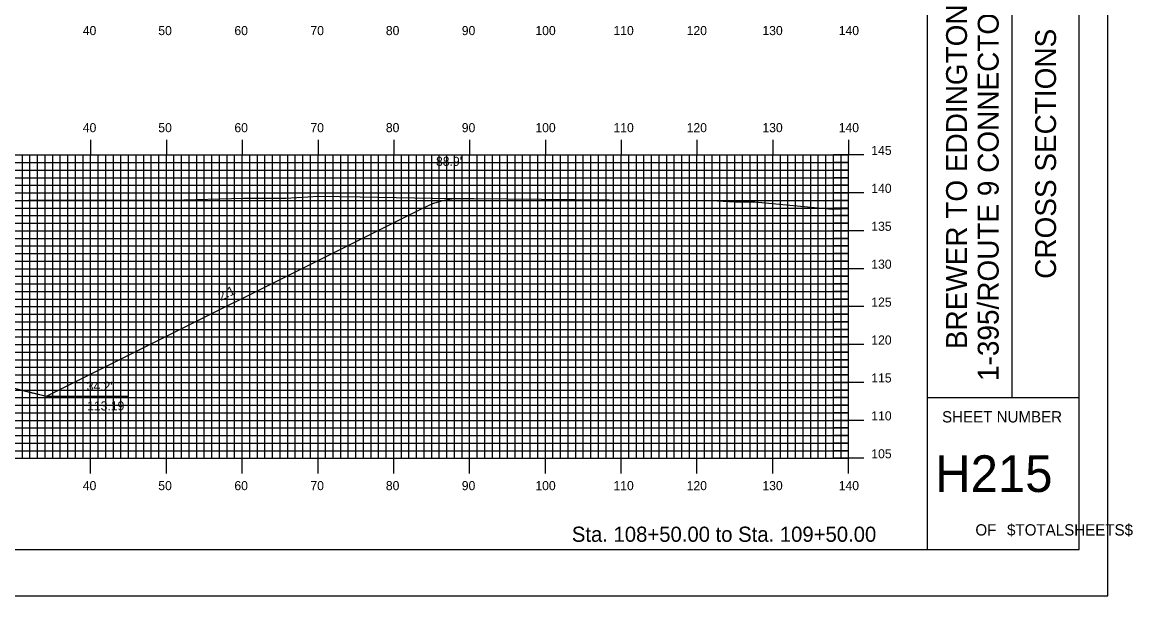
# Model space of a CAD drawing. Extents: x 1768874 to 1769217, y 442591 to 442811.
# Drawn here: x 1769071 to 1769217.5, y 442590.5 to 442666.2 of the extents above; entities that cross this region are included whole.
import ezdxf

# ---------------------------------------------------------------- set-up
doc = ezdxf.new("R2010")
doc.units = 0
for name, color, linetype in [('ANNOTATION', 7, 'Continuous'), ('BORDER', 7, 'Continuous'), ('D_Roadway_Centerline', 7, 'Continuous'), ('D_Roadway_SlopeLines', 7, 'Continuous'), ('D_Text_Standard', 7, 'Continuous'), ('H_V ANNOTATION', 7, 'Continuous'), ('MAJOR', 7, 'Continuous'), ('MINOR', 7, 'Continuous'), ('PDRAIN', 7, 'Continuous'), ('PLOT BOUNDARY', 7, 'Continuous'), ('S_Roadway_Centerline', 7, 'Continuous')]:
    doc.layers.add(name, color=color, linetype=linetype)

msp = doc.modelspace()

# ---------------------------------------------------------------- linework, layer by layer
at = {"layer": 'BORDER'}
for p, q in [((1769190.39, 442596.67), (1769190.39, 442806.67)), ((1769201.57, 442616.67), (1769201.57, 442686.67)), ((1769190.39, 442616.67), (1769210.39, 442616.67))]:
    msp.add_line(p, q, dxfattribs=at)
msp.add_lwpolyline([(1768890.39, 442596.67), (1769210.39, 442596.67), (1769210.39, 442806.67), (1768890.39, 442806.67)], close=True, dxfattribs=at)
at = {"layer": 'D_Roadway_Centerline'}
msp.add_lwpolyline([(1769070.16, 442617.85), (1769072.1, 442617.37), (1769074.16, 442616.85), (1769074.16, 442616.85), (1769123.9, 442641.72), (1769125.15, 442642.27), (1769126.4, 442642.65), (1769127.09, 442642.78), (1769127.65, 442642.88), (1769128.75, 442642.94), (1769128.9, 442642.95)], dxfattribs=at)
at = {"layer": 'D_Roadway_SlopeLines'}
for points in [[(1769074.16, 442616.85), (1769123.9, 442641.72), (1769125.15, 442642.27), (1769126.4, 442642.65), (1769127.65, 442642.88), (1769128.9, 442642.95)], [(1769059.99, 442620.4), (1769074.16, 442616.85)]]:
    msp.add_lwpolyline(points, dxfattribs=at)
at = {"layer": 'MAJOR'}
for p, q in [((1769079.99, 442650.67), (1769079.99, 442648.67)), ((1769089.99, 442650.67), (1769089.99, 442648.67)), ((1769099.99, 442650.67), (1769099.99, 442648.67)), ((1769109.99, 442650.67), (1769109.99, 442648.67)), ((1769119.99, 442650.67), (1769119.99, 442648.67)), ((1769129.99, 442650.67), (1769129.99, 442648.67)), ((1769139.99, 442650.67), (1769139.99, 442648.67)), ((1769149.99, 442650.67), (1769149.99, 442648.67)), ((1769159.99, 442650.67), (1769159.99, 442648.67)), ((1769169.99, 442650.67), (1769169.99, 442648.67)), ((1769179.99, 442650.67), (1769179.99, 442648.67)), ((1768899.99, 442648.67), (1769179.99, 442648.67)), ((1768899.99, 442648.67), (1769179.99, 442648.67)), ((1769079.99, 442608.67), (1769079.99, 442648.67)), ((1769089.99, 442608.67), (1769089.99, 442648.67)), ((1769099.99, 442608.67), (1769099.99, 442648.67)), ((1769109.99, 442608.67), (1769109.99, 442648.67)), ((1769119.99, 442608.67), (1769119.99, 442648.67)), ((1769129.99, 442608.67), (1769129.99, 442648.67)), ((1769139.99, 442608.67), (1769139.99, 442648.67)), ((1769149.99, 442608.67), (1769149.99, 442648.67)), ((1769159.99, 442608.67), (1769159.99, 442648.67)), ((1769169.99, 442608.67), (1769169.99, 442648.67)), ((1769181.99, 442648.67), (1769177.98, 442648.67)), ((1769179.99, 442608.67), (1769179.99, 442648.67)), ((1769179.99, 442608.67), (1769179.99, 442648.67)), ((1768899.99, 442643.67), (1769179.99, 442643.67)), ((1769181.99, 442643.67), (1769177.98, 442643.67)), ((1768899.99, 442638.67), (1769179.99, 442638.67)), ((1769181.99, 442638.67), (1769177.98, 442638.67)), ((1768899.99, 442633.67), (1769179.99, 442633.67)), ((1769181.99, 442633.67), (1769177.98, 442633.67)), ((1768899.99, 442628.67), (1769179.99, 442628.67)), ((1769181.99, 442628.67), (1769177.98, 442628.67)), ((1768899.99, 442623.67), (1769179.99, 442623.67)), ((1769181.99, 442623.67), (1769177.98, 442623.67)), ((1768899.99, 442618.67), (1769179.99, 442618.67)), ((1769181.99, 442618.67), (1769177.98, 442618.67)), ((1768899.99, 442613.67), (1769179.99, 442613.67)), ((1769181.99, 442613.67), (1769177.98, 442613.67)), ((1768899.99, 442608.67), (1769179.99, 442608.67)), ((1768899.99, 442608.67), (1769179.99, 442608.67)), ((1769079.99, 442606.66), (1769079.99, 442608.67)), ((1769089.99, 442606.66), (1769089.99, 442608.67)), ((1769099.99, 442606.66), (1769099.99, 442608.67)), ((1769109.99, 442606.66), (1769109.99, 442608.67)), ((1769119.99, 442606.66), (1769119.99, 442608.67)), ((1769129.99, 442606.66), (1769129.99, 442608.67)), ((1769139.99, 442606.66), (1769139.99, 442608.67)), ((1769149.99, 442606.66), (1769149.99, 442608.67)), ((1769159.99, 442606.66), (1769159.99, 442608.67)), ((1769169.99, 442606.66), (1769169.99, 442608.67)), ((1769181.99, 442608.67), (1769177.98, 442608.67)), ((1769179.99, 442606.66), (1769179.99, 442608.67))]:
    msp.add_line(p, q, dxfattribs=at)
at = {"layer": 'MINOR'}
for p, q in [((1769070.99, 442608.67), (1769070.99, 442648.67)), ((1769071.99, 442608.67), (1769071.99, 442648.67)), ((1769072.99, 442608.67), (1769072.99, 442648.67)), ((1769073.99, 442608.67), (1769073.99, 442648.67)), ((1769074.99, 442608.67), (1769074.99, 442648.67)), ((1769075.99, 442608.67), (1769075.99, 442648.67)), ((1769076.99, 442608.67), (1769076.99, 442648.67)), ((1769077.99, 442608.67), (1769077.99, 442648.67)), ((1769078.99, 442608.67), (1769078.99, 442648.67)), ((1769080.99, 442608.67), (1769080.99, 442648.67)), ((1769081.99, 442608.67), (1769081.99, 442648.67)), ((1769082.99, 442608.67), (1769082.99, 442648.67)), ((1769083.99, 442608.67), (1769083.99, 442648.67)), ((1769084.99, 442608.67), (1769084.99, 442648.67)), ((1769085.99, 442608.67), (1769085.99, 442648.67)), ((1769086.99, 442608.67), (1769086.99, 442648.67)), ((1769087.99, 442608.67), (1769087.99, 442648.67)), ((1769088.99, 442608.67), (1769088.99, 442648.67)), ((1769090.99, 442608.67), (1769090.99, 442648.67)), ((1769091.99, 442608.67), (1769091.99, 442648.67)), ((1769092.99, 442608.67), (1769092.99, 442648.67)), ((1769093.99, 442608.67), (1769093.99, 442648.67)), ((1769094.99, 442608.67), (1769094.99, 442648.67)), ((1769095.99, 442608.67), (1769095.99, 442648.67)), ((1769096.99, 442608.67), (1769096.99, 442648.67)), ((1769097.99, 442608.67), (1769097.99, 442648.67)), ((1769098.99, 442608.67), (1769098.99, 442648.67)), ((1769100.99, 442608.67), (1769100.99, 442648.67)), ((1769101.99, 442608.67), (1769101.99, 442648.67)), ((1769102.99, 442608.67), (1769102.99, 442648.67)), ((1769103.99, 442608.67), (1769103.99, 442648.67)), ((1769104.99, 442608.67), (1769104.99, 442648.67)), ((1769105.99, 442608.67), (1769105.99, 442648.67)), ((1769106.99, 442608.67), (1769106.99, 442648.67)), ((1769107.99, 442608.67), (1769107.99, 442648.67)), ((1769108.99, 442608.67), (1769108.99, 442648.67)), ((1769110.99, 442608.67), (1769110.99, 442648.67)), ((1769111.99, 442608.67), (1769111.99, 442648.67)), ((1769112.99, 442608.67), (1769112.99, 442648.67)), ((1769113.99, 442608.67), (1769113.99, 442648.67)), ((1769114.99, 442608.67), (1769114.99, 442648.67)), ((1769115.99, 442608.67), (1769115.99, 442648.67)), ((1769116.99, 442608.67), (1769116.99, 442648.67)), ((1769117.99, 442608.67), (1769117.99, 442648.67)), ((1769118.99, 442608.67), (1769118.99, 442648.67)), ((1769120.99, 442608.67), (1769120.99, 442648.67)), ((1769121.99, 442608.67), (1769121.99, 442648.67)), ((1769122.99, 442608.67), (1769122.99, 442648.67)), ((1769123.99, 442608.67), (1769123.99, 442648.67)), ((1769124.99, 442608.67), (1769124.99, 442648.67)), ((1769125.99, 442608.67), (1769125.99, 442648.67)), ((1769126.99, 442608.67), (1769126.99, 442648.67)), ((1769127.99, 442608.67), (1769127.99, 442648.67)), ((1769128.99, 442608.67), (1769128.99, 442648.67)), ((1769130.99, 442608.67), (1769130.99, 442648.67)), ((1769131.99, 442608.67), (1769131.99, 442648.67)), ((1769132.99, 442608.67), (1769132.99, 442648.67)), ((1769133.99, 442608.67), (1769133.99, 442648.67)), ((1769134.99, 442608.67), (1769134.99, 442648.67)), ((1769135.99, 442608.67), (1769135.99, 442648.67)), ((1769136.99, 442608.67), (1769136.99, 442648.67)), ((1769137.99, 442608.67), (1769137.99, 442648.67)), ((1769138.99, 442608.67), (1769138.99, 442648.67)), ((1769140.99, 442608.67), (1769140.99, 442648.67)), ((1769141.99, 442608.67), (1769141.99, 442648.67)), ((1769142.99, 442608.67), (1769142.99, 442648.67)), ((1769143.99, 442608.67), (1769143.99, 442648.67)), ((1769144.99, 442608.67), (1769144.99, 442648.67)), ((1769145.99, 442608.67), (1769145.99, 442648.67)), ((1769146.99, 442608.67), (1769146.99, 442648.67)), ((1769147.99, 442608.67), (1769147.99, 442648.67)), ((1769148.99, 442608.67), (1769148.99, 442648.67)), ((1769150.99, 442608.67), (1769150.99, 442648.67)), ((1769151.99, 442608.67), (1769151.99, 442648.67)), ((1769152.99, 442608.67), (1769152.99, 442648.67)), ((1769153.99, 442608.67), (1769153.99, 442648.67)), ((1769154.99, 442608.67), (1769154.99, 442648.67)), ((1769155.99, 442608.67), (1769155.99, 442648.67)), ((1769156.99, 442608.67), (1769156.99, 442648.67)), ((1769157.99, 442608.67), (1769157.99, 442648.67)), ((1769158.99, 442608.67), (1769158.99, 442648.67)), ((1769160.99, 442608.67), (1769160.99, 442648.67)), ((1769161.99, 442608.67), (1769161.99, 442648.67)), ((1769162.99, 442608.67), (1769162.99, 442648.67)), ((1769163.99, 442608.67), (1769163.99, 442648.67)), ((1769164.99, 442608.67), (1769164.99, 442648.67)), ((1769165.99, 442608.67), (1769165.99, 442648.67)), ((1769166.99, 442608.67), (1769166.99, 442648.67)), ((1769167.99, 442608.67), (1769167.99, 442648.67)), ((1769168.99, 442608.67), (1769168.99, 442648.67)), ((1769170.99, 442608.67), (1769170.99, 442648.67)), ((1769171.99, 442608.67), (1769171.99, 442648.67)), ((1769172.99, 442608.67), (1769172.99, 442648.67)), ((1769173.99, 442608.67), (1769173.99, 442648.67)), ((1769174.99, 442608.67), (1769174.99, 442648.67)), ((1769175.99, 442608.67), (1769175.99, 442648.67)), ((1769176.99, 442608.67), (1769176.99, 442648.67)), ((1769177.99, 442608.67), (1769177.99, 442648.67)), ((1769178.99, 442608.67), (1769178.99, 442648.67)), ((1768899.99, 442647.67), (1769179.99, 442647.67)), ((1768899.99, 442646.67), (1769179.99, 442646.67)), ((1769179.99, 442647.67), (1769177.98, 442647.67)), ((1769179.99, 442646.67), (1769177.98, 442646.67)), ((1768899.99, 442645.67), (1769179.99, 442645.67)), ((1769179.99, 442645.67), (1769177.98, 442645.67)), ((1768899.99, 442644.67), (1769179.99, 442644.67)), ((1769179.99, 442644.67), (1769177.98, 442644.67)), ((1768899.99, 442642.67), (1769179.99, 442642.67)), ((1769179.99, 442642.67), (1769177.98, 442642.67)), ((1768899.99, 442641.67), (1769179.99, 442641.67)), ((1768899.99, 442640.67), (1769179.99, 442640.67)), ((1769179.99, 442641.67), (1769177.98, 442641.67)), ((1769179.99, 442640.67), (1769177.98, 442640.67)), ((1768899.99, 442639.67), (1769179.99, 442639.67)), ((1769179.99, 442639.67), (1769177.98, 442639.67)), ((1768899.99, 442637.67), (1769179.99, 442637.67)), ((1769179.99, 442637.67), (1769177.98, 442637.67)), ((1768899.99, 442636.67), (1769179.99, 442636.67)), ((1769179.99, 442636.67), (1769177.98, 442636.67)), ((1768899.99, 442635.67), (1769179.99, 442635.67)), ((1769179.99, 442635.67), (1769177.98, 442635.67)), ((1768899.99, 442634.67), (1769179.99, 442634.67)), ((1769179.99, 442634.67), (1769177.98, 442634.67)), ((1768899.99, 442632.67), (1769179.99, 442632.67)), ((1769179.99, 442632.67), (1769177.98, 442632.67)), ((1768899.99, 442631.67), (1769179.99, 442631.67)), ((1768899.99, 442630.67), (1769179.99, 442630.67)), ((1769179.99, 442631.67), (1769177.98, 442631.67)), ((1769179.99, 442630.67), (1769177.98, 442630.67)), ((1768899.99, 442629.67), (1769179.99, 442629.67)), ((1769179.99, 442629.67), (1769177.98, 442629.67)), ((1768899.99, 442627.67), (1769179.99, 442627.67)), ((1769179.99, 442627.67), (1769177.98, 442627.67)), ((1768899.99, 442626.67), (1769179.99, 442626.67)), ((1769179.99, 442626.67), (1769177.98, 442626.67)), ((1768899.99, 442625.67), (1769179.99, 442625.67)), ((1768899.99, 442624.67), (1769179.99, 442624.67)), ((1769179.99, 442625.67), (1769177.98, 442625.67)), ((1769179.99, 442624.67), (1769177.98, 442624.67)), ((1768899.99, 442622.67), (1769179.99, 442622.67)), ((1768899.99, 442621.67), (1769179.99, 442621.67)), ((1769179.99, 442622.67), (1769177.98, 442622.67)), ((1769179.99, 442621.67), (1769177.98, 442621.67)), ((1768899.99, 442620.67), (1769179.99, 442620.67)), ((1769179.99, 442620.67), (1769177.98, 442620.67)), ((1768899.99, 442619.67), (1769179.99, 442619.67)), ((1769179.99, 442619.67), (1769177.98, 442619.67)), ((1768899.99, 442617.67), (1769179.99, 442617.67)), ((1769179.99, 442617.67), (1769177.98, 442617.67)), ((1768899.99, 442616.67), (1769179.99, 442616.67)), ((1768899.99, 442615.67), (1769179.99, 442615.67)), ((1769179.99, 442616.67), (1769177.98, 442616.67)), ((1769179.99, 442615.67), (1769177.98, 442615.67)), ((1768899.99, 442614.67), (1769179.99, 442614.67)), ((1769179.99, 442614.67), (1769177.98, 442614.67)), ((1768899.99, 442612.67), (1769179.99, 442612.67)), ((1768899.99, 442611.67), (1769179.99, 442611.67)), ((1769179.99, 442612.67), (1769177.98, 442612.67)), ((1769179.99, 442611.67), (1769177.98, 442611.67)), ((1768899.99, 442610.67), (1769179.99, 442610.67)), ((1769179.99, 442610.67), (1769177.98, 442610.67)), ((1768899.99, 442609.67), (1769179.99, 442609.67)), ((1769179.99, 442609.67), (1769177.98, 442609.67))]:
    msp.add_line(p, q, dxfattribs=at)
at = {"layer": 'PDRAIN'}
msp.add_line((1769074.16, 442616.85), (1769084.93, 442616.85), dxfattribs=at)
at = {"layer": 'PLOT BOUNDARY'}
msp.add_lwpolyline([(1768874.2, 442590.55), (1769214.2, 442590.55), (1769214.2, 442810.55), (1768874.2, 442810.55)], close=True, dxfattribs=at)
at = {"layer": 'S_Roadway_Centerline'}
msp.add_lwpolyline([(1769069.58, 442642.66), (1769071.5, 442642.66), (1769071.78, 442642.7), (1769081.83, 442642.71), (1769090.7, 442642.72), (1769100.18, 442642.96), (1769105.74, 442642.99), (1769110.09, 442643.24), (1769115.57, 442643.17), (1769127.48, 442642.95), (1769128.69, 442642.95), (1769129.35, 442642.94), (1769130.53, 442642.93), (1769148.39, 442642.74), (1769162.71, 442642.63), (1769164.9, 442642.49), (1769167.63, 442642.49), (1769177.83, 442641.53), (1769179.99, 442641.59)], dxfattribs=at)

# ---------------------------------------------------------------- texts
at = {"layer": 'ANNOTATION'}
msp.add_text('2:1', height=1.2, rotation=26.5653, dxfattribs=at).set_placement((1769097.18, 442629.4))
for s, p in [("34.2'", (1769079.47, 442617.58)), ('113.19', (1769079.53, 442614.98))]:
    msp.add_text(s, height=1.2, dxfattribs=at).set_placement(p)
at = {"layer": 'BORDER'}
for s, p in [('1-395/ROUTE 9 CONNECTOR', (1769199.79, 442618.87)), ('BREWER TO EDDINGTON', (1769195.61, 442623.07)), ('CROSS SECTIONS', (1769207.36, 442632.34))]:
    msp.add_text(s, height=2.7557, rotation=90, dxfattribs=at).set_placement(p)
for s, height, p in [('SHEET NUMBER', 1.4905, (1769192.32, 442613.4)), ('H215', 4.839, (1769191.42, 442604.23)), ('OF', 1.491, (1769196.72, 442598.49)), ('$TOTALSHEETS$', 1.4905, (1769200.9, 442598.49))]:
    msp.add_text(s, height=height, dxfattribs=at).set_placement(p)
at = {"layer": 'D_Text_Standard'}
msp.add_text("88.9'", height=1.2, dxfattribs=at).set_placement((1769125.56, 442647.23))
at = {"layer": 'H_V ANNOTATION'}
for s, height, p in [('40', 1.2, (1769078.96, 442664.47)), ('50', 1.2, (1769088.92, 442664.47)), ('60', 1.2, (1769098.96, 442664.47)), ('70', 1.2, (1769108.99, 442664.47)), ('80', 1.2, (1769118.94, 442664.47)), ('90', 1.2, (1769128.96, 442664.47)), ('100', 1.2, (1769138.67, 442664.47)), ('110', 1.2, (1769148.97, 442664.47)), ('120', 1.2, (1769158.63, 442664.47)), ('130', 1.2, (1769168.62, 442664.47)), ('140', 1.2, (1769178.69, 442664.47)), ('40', 1.2, (1769078.96, 442651.67)), ('50', 1.2, (1769088.92, 442651.67)), ('60', 1.2, (1769098.96, 442651.67)), ('70', 1.2, (1769108.99, 442651.67)), ('80', 1.2, (1769118.94, 442651.67)), ('90', 1.2, (1769128.96, 442651.67)), ('100', 1.2, (1769138.67, 442651.67)), ('110', 1.2, (1769148.97, 442651.67)), ('120', 1.2, (1769158.63, 442651.67)), ('130', 1.2, (1769168.62, 442651.67)), ('140', 1.2, (1769178.69, 442651.67)), ('145', 1.2, (1769182.99, 442648.67)), ('140', 1.2, (1769182.99, 442643.67)), ('135', 1.2, (1769182.99, 442638.67)), ('130', 1.2, (1769182.99, 442633.67)), ('125', 1.2, (1769182.99, 442628.67)), ('120', 1.2, (1769182.99, 442623.67)), ('115', 1.2, (1769182.99, 442618.67)), ('110', 1.2, (1769182.99, 442613.67)), ('105', 1.2, (1769182.99, 442608.67)), ('40', 1.2, (1769078.96, 442604.47)), ('50', 1.2, (1769088.92, 442604.47)), ('60', 1.2, (1769098.96, 442604.47)), ('70', 1.2, (1769108.99, 442604.47)), ('80', 1.2, (1769118.94, 442604.47)), ('90', 1.2, (1769128.96, 442604.47)), ('100', 1.2, (1769138.67, 442604.47)), ('110', 1.2, (1769148.97, 442604.47)), ('120', 1.2, (1769158.63, 442604.47)), ('130', 1.2, (1769168.62, 442604.47)), ('140', 1.2, (1769178.69, 442604.47)), ('Sta. 108+50.00 to Sta. 109+50.00', 2.0004, (1769143.48, 442597.66))]:
    msp.add_text(s, height=height, dxfattribs=at).set_placement(p)

doc.saveas('drawing.dxf')
